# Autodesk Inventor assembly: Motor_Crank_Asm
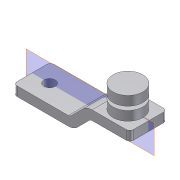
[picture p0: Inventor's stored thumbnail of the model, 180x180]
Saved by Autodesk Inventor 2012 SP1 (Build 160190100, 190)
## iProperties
Created: 2006-03
Part Number: Motor_Crank_Asm
Document SubType Name: Assembly
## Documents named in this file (3)
- D:\Backup\Autodesk Motion Files\Inv2012DynSim\Sub-Assemblies\Motor_Crank_Asm.iam
- D:\Backup\Autodesk Motion Files\Inv2012DynSim\Parts\Crank_motor.ipt
- D:\Backup\Autodesk Motion Files\Inv2012DynSim\Parts\Pawn_1.ipt
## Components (2 placed, 2 different names)
1. Crank_motor:1 — Mate:1, Mate:2
2. Pawn_1:1 — Mate:1, Mate:2
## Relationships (2: Mate 2)
- Mate:1: Crank_motor:1 ↔ Pawn_1:1
- Mate:2: Crank_motor:1 ↔ Pawn_1:1
